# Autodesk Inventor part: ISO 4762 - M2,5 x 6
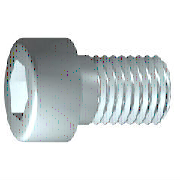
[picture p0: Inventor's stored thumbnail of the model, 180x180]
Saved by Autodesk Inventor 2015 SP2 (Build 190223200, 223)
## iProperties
IsCustomPart: 0
Created: 2012-02
Part Number: ISO 4762 - M2,5 x 6
Material: Stainless Steel, 440C
Description: Hexagon Socket Head Cap Screw
Document SubType Name: Modeling
Standard: ISO 4762
Designer: rYan
Standard Revision: 1998
Standards Organization: DIN
Language: en-US
Size Designation: M2,5 x 6
Categories: <MemberInstance><Categories><Category DisplayName="Fasteners" InternalName="e4da775c-781d-43d5-af7c-5136215cf5a6" Mnemonic="FSTN"><Category DisplayName="Bolts"
Density: 7.75 g/cm^3
Mass: 0.496406 g
Surface Area: 1.19592 cm^2
Volume: 0.0640524 cm^3
Appearance: Halbpoliert
Author: rYan
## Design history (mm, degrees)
sketch "Sketch1"
  geometry: L1 (-0.733, 0)-(6, 0); L2 (6, 0)-(6, 1.25); L3 (6, 1.25)-(1.125, 1.25); L4 (1.125, 1.25)-(0.849, 1.25); L5 (0.849, 1.25)-(0, 1.25); L6 (0, 1.25)-(0, 2.25); L7 (0, 2.25)-(-2.5, 2.25); L8 (-2.5, 2.25)-(-2.5, 1.155); L9 (-2.5, 1.155)-(-1.4, 1.155); L10 (-1.4, 1.155)-(-0.733, 0); L11 (-4.2, 0)-(7.7, 0) reference; L12 (0, -0.45)-(0, 2.7) reference; L13 (1.125, 1.25)-(0, 1.25)
  constraints: 22 end point, 6 parallel, 2 collinear, 2 perpendicular, 1 horizontal, 1 point on line
  dimensions: "d1" = 4.875 distance from line of L3.end L2 (= GEL); "d2" = 0.27615 distance of L4.end L3.end (computed from GAL); "d3" = 2.5 distance between parallel lines of L8 L6 (= KOH); "d4" = 1.1 distance of L8.end L9.end (= INTI); "d5" = 60 deg angle of L10 L1; "d6" = 2.5 diameter of L3 L1 (= GD); "d7" = 2.5 diameter of L5 L1 (= BDM); "d8" = 2.3094 diameter of L9 L1 (= 1.1547 x SW); "d9" = 4.5 diameter of L7 L1 (= KOD); "d26" = 6 distance between parallel lines of L12 L2 (= NLG)
revolve "Body" sketch "Sketch1" stored, may be unused: angle "d10" = 90 deg
sketch "Sketch2"
  geometry: L1 (0, -3.15)-(0, 3.15) reference; L2 (-3.15, 0)-(3.15, 0) reference; L3 (1.155, 0)-(0.577, -1); L4 (0.577, -1)-(-0.577, -1); L5 (-0.577, -1)-(-1.155, 0); L6 (-1.155, 0)-(-0.577, 1); L7 (-0.577, 1)-(0.577, 1); L8 (0.577, 1)-(1.155, 0); 2 further points
  constraints: 12 end point, 1 coincident, 1 horizontal alignment, 1 point on line, 12 other
extrude "Slot" join sketch "Sketch2" stored distance "d11" = 10; taper "d12" = 0 deg
fillet "Fillet1" dims "d17" = 0.25 (= RR)
feature "Thread" dims "d13" = 4.875 (= GEL), "d14" = 0
chamfer "Chamfer1" distance "d15" = 0.27605 (= -0.5 x SPD + 0.5 x GD); stored, may be unused: second distance "d16" = 0.27605 (= GUL), angle "d27" = 45 deg
workplane "Work Plane1"
fillet "Fillet2" dims "d30" = 0.1 (= R)
body "Solid1"
other parameters: "GD" = 2.5 [user parameter; used in 2 equation terms], "NLG" = 6 [user parameter; used in 1 equation term], "GEL" = 4.875 [user parameter; used in 2 equation terms], "KOD" = 4.5 [user parameter; used in 1 equation term], "KOH" = 2.5 [user parameter; used in 1 equation term], "INTI" = 1.1 [user parameter; used in 1 equation term], "GAL" = 0.27605 (= 0.61345 x PTC) [user parameter; used in 1 equation term], "GUL" = 0.27605 (= 0.61345 x PTC) [user parameter; used in 1 equation term], "BDM" = 2.5 (= NND) [user parameter; used in 1 equation term], "SW" = 2 [user parameter; used in 2 equation terms], "RR" = 0.25 [user parameter; used in 1 equation term], "SPD" = 1.94789 (= NND - 1.2269 x PTC) [user parameter; used in 1 equation term], "d19" = 0, "d28" = 0, "d29" = 0, "R" = 0.1 [user parameter; used in 1 equation term], "TOA" = 30 deg [user parameter], "GD1" = 1.94789 (= THREADDIA - 1.2269 x PTC) [user parameter], "THREADDIA" = 2.5 [user parameter; used in 1 equation term], "FAWI" = 45 deg [user parameter], "TPU" = 22.22222 (computed from PTC) [user parameter], "PTC" = 0.45 [user parameter; used in 5 equation terms], "NND" = 2.5 [user parameter; used in 2 equation terms], "E0" = 2.31 (= 1.155 x SW) [user parameter]
